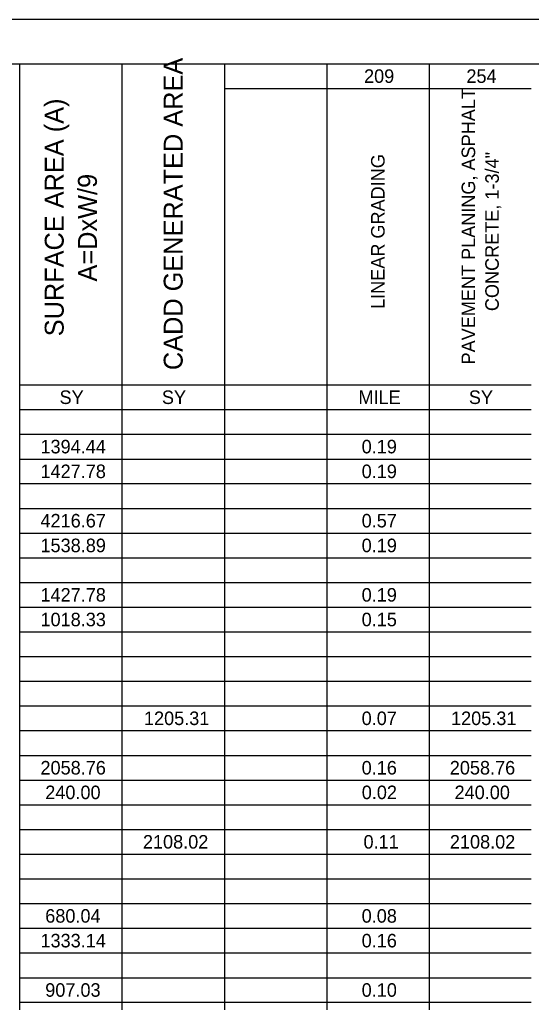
# Model space of a CAD drawing. Extents: x 0 to 34, y 0 to 22.
# Drawn here: x 10.58 to 16.38, y 10.87 to 22 of the extents above; entities that cross this region are included whole.
import ezdxf

# ---------------------------------------------------------------- set-up
doc = ezdxf.new("R2010")
doc.units = 0
for name, color, linetype in [('SH_Border', 7, 'Continuous'), ('SH_Cut_Line', 7, 'Continuous'), ('SH_Text', 7, 'Continuous')]:
    doc.layers.add(name, color=color, linetype=linetype)

msp = doc.modelspace()

# ---------------------------------------------------------------- linework, layer by layer
at = {"layer": 'SH_Border'}
msp.add_lwpolyline([(1.5, 21.5), (33.5, 21.5), (33.5, 0.5), (1.5, 0.5)], close=True, dxfattribs=at)
at = {"layer": 'SH_Cut_Line'}
msp.add_lwpolyline([(0, 0), (34, 0), (34, 22), (0, 22)], close=True, dxfattribs=at)
at = {"layer": 'SH_Text'}
for p, q in [((10.584, 21.5), (11.743, 21.5)), ((10.584, 21.5), (10.584, 21.22)), ((11.743, 21.5), (14.061, 21.5)), ((11.743, 21.5), (11.743, 21.22)), ((12.902, 21.5), (12.902, 21.22)), ((14.061, 21.5), (15.22, 21.5)), ((14.061, 21.5), (14.061, 21.22)), ((15.22, 21.5), (16.378, 21.5)), ((15.22, 21.5), (15.22, 21.22)), ((10.584, 21.22), (10.584, 20.941)), ((11.743, 21.22), (11.743, 20.941)), ((12.902, 21.22), (14.061, 21.22)), ((12.902, 21.22), (12.902, 20.941)), ((14.061, 21.22), (15.22, 21.22)), ((14.061, 21.22), (14.061, 20.941)), ((15.22, 21.22), (16.378, 21.22)), ((15.22, 21.22), (15.22, 20.941)), ((10.584, 20.941), (10.584, 20.661)), ((11.743, 20.941), (11.743, 20.661)), ((12.902, 20.941), (12.902, 20.661)), ((14.061, 20.941), (14.061, 20.661)), ((15.22, 20.941), (15.22, 20.661)), ((10.584, 20.661), (10.584, 20.381)), ((11.743, 20.661), (11.743, 20.381)), ((12.902, 20.661), (12.902, 20.381)), ((14.061, 20.661), (14.061, 20.381)), ((15.22, 20.661), (15.22, 20.381)), ((10.584, 20.381), (10.584, 20.101)), ((11.743, 20.381), (11.743, 20.101)), ((12.902, 20.381), (12.902, 20.101)), ((14.061, 20.381), (14.061, 20.101)), ((15.22, 20.381), (15.22, 20.101)), ((10.584, 20.101), (10.584, 19.822)), ((11.743, 20.101), (11.743, 19.822)), ((12.902, 20.101), (12.902, 19.822)), ((14.061, 20.101), (14.061, 19.822)), ((15.22, 20.101), (15.22, 19.822)), ((10.584, 19.822), (10.584, 19.542)), ((11.743, 19.822), (11.743, 19.542)), ((12.902, 19.822), (12.902, 19.542)), ((14.061, 19.822), (14.061, 19.542)), ((15.22, 19.822), (15.22, 19.542)), ((10.584, 19.542), (10.584, 19.262)), ((11.743, 19.542), (11.743, 19.262)), ((12.902, 19.542), (12.902, 19.262)), ((14.061, 19.542), (14.061, 19.262)), ((15.22, 19.542), (15.22, 19.262)), ((10.584, 19.262), (10.584, 18.983)), ((11.743, 19.262), (11.743, 18.983)), ((12.902, 19.262), (12.902, 18.983)), ((14.061, 19.262), (14.061, 18.983)), ((15.22, 19.262), (15.22, 18.983)), ((10.584, 18.983), (10.584, 18.703)), ((11.743, 18.983), (11.743, 18.703)), ((12.902, 18.983), (12.902, 18.703)), ((14.061, 18.983), (14.061, 18.703)), ((15.22, 18.983), (15.22, 18.703)), ((10.584, 18.703), (10.584, 18.423)), ((11.743, 18.703), (11.743, 18.423)), ((12.902, 18.703), (12.902, 18.423)), ((14.061, 18.703), (14.061, 18.423)), ((15.22, 18.703), (15.22, 18.423)), ((10.584, 18.423), (10.584, 18.143)), ((11.743, 18.423), (11.743, 18.143)), ((12.902, 18.423), (12.902, 18.143)), ((14.061, 18.423), (14.061, 18.143)), ((15.22, 18.423), (15.22, 18.143)), ((10.584, 18.143), (10.584, 17.864)), ((11.743, 18.143), (11.743, 17.864)), ((12.902, 18.143), (12.902, 17.864)), ((14.061, 18.143), (14.061, 17.864)), ((15.22, 18.143), (15.22, 17.864)), ((10.584, 17.864), (11.743, 17.864)), ((10.584, 17.864), (10.584, 17.584)), ((11.743, 17.864), (14.061, 17.864)), ((11.743, 17.864), (11.743, 17.584)), ((12.902, 17.864), (12.902, 17.584)), ((14.061, 17.864), (15.22, 17.864)), ((14.061, 17.864), (14.061, 17.584)), ((15.22, 17.864), (16.378, 17.864)), ((15.22, 17.864), (15.22, 17.584)), ((10.584, 17.584), (11.743, 17.584)), ((10.584, 17.584), (10.584, 17.304)), ((11.743, 17.584), (14.061, 17.584)), ((11.743, 17.584), (11.743, 17.304)), ((12.902, 17.584), (12.902, 17.304)), ((14.061, 17.584), (15.22, 17.584)), ((14.061, 17.584), (14.061, 17.304)), ((15.22, 17.584), (16.378, 17.584)), ((15.22, 17.584), (15.22, 17.304)), ((10.584, 17.304), (11.743, 17.304)), ((10.584, 17.304), (10.584, 17.024)), ((11.743, 17.304), (14.061, 17.304)), ((11.743, 17.304), (11.743, 17.024)), ((12.902, 17.304), (12.902, 17.024)), ((14.061, 17.304), (15.22, 17.304)), ((14.061, 17.304), (14.061, 17.024)), ((15.22, 17.304), (16.378, 17.304)), ((15.22, 17.304), (15.22, 17.024)), ((10.584, 17.024), (11.743, 17.024)), ((10.584, 17.024), (10.584, 16.745)), ((11.743, 17.024), (14.061, 17.024)), ((11.743, 17.024), (11.743, 16.745)), ((12.902, 17.024), (12.902, 16.745)), ((14.061, 17.024), (15.22, 17.024)), ((14.061, 17.024), (14.061, 16.745)), ((15.22, 17.024), (16.378, 17.024)), ((15.22, 17.024), (15.22, 16.745)), ((10.584, 16.745), (11.743, 16.745)), ((10.584, 16.745), (10.584, 16.465)), ((11.743, 16.745), (14.061, 16.745)), ((11.743, 16.745), (11.743, 16.465)), ((12.902, 16.745), (12.902, 16.465)), ((14.061, 16.745), (15.22, 16.745)), ((14.061, 16.745), (14.061, 16.465)), ((15.22, 16.745), (16.378, 16.745)), ((15.22, 16.745), (15.22, 16.465)), ((10.584, 16.465), (11.743, 16.465)), ((10.584, 16.465), (10.584, 16.185)), ((11.743, 16.465), (14.061, 16.465)), ((11.743, 16.465), (11.743, 16.185)), ((12.902, 16.465), (12.902, 16.185)), ((14.061, 16.465), (15.22, 16.465)), ((14.061, 16.465), (14.061, 16.185)), ((15.22, 16.465), (16.378, 16.465)), ((15.22, 16.465), (15.22, 16.185)), ((10.584, 16.185), (11.743, 16.185)), ((10.584, 16.185), (10.584, 15.906)), ((11.743, 16.185), (14.061, 16.185)), ((11.743, 16.185), (11.743, 15.906)), ((12.902, 16.185), (12.902, 15.906)), ((14.061, 16.185), (15.22, 16.185)), ((14.061, 16.185), (14.061, 15.906)), ((15.22, 16.185), (16.378, 16.185)), ((15.22, 16.185), (15.22, 15.906)), ((10.584, 15.906), (11.743, 15.906)), ((10.584, 15.906), (10.584, 15.626)), ((11.743, 15.906), (14.061, 15.906)), ((11.743, 15.906), (11.743, 15.626)), ((12.902, 15.906), (12.902, 15.626)), ((14.061, 15.906), (15.22, 15.906)), ((14.061, 15.906), (14.061, 15.626)), ((15.22, 15.906), (16.378, 15.906)), ((15.22, 15.906), (15.22, 15.626)), ((10.584, 15.626), (11.743, 15.626)), ((10.584, 15.626), (10.584, 15.346)), ((11.743, 15.626), (14.061, 15.626)), ((11.743, 15.626), (11.743, 15.346)), ((12.902, 15.626), (12.902, 15.346)), ((14.061, 15.626), (15.22, 15.626)), ((14.061, 15.626), (14.061, 15.346)), ((15.22, 15.626), (16.378, 15.626)), ((15.22, 15.626), (15.22, 15.346)), ((10.584, 15.346), (11.743, 15.346)), ((10.584, 15.346), (10.584, 15.066)), ((11.743, 15.346), (14.061, 15.346)), ((11.743, 15.346), (11.743, 15.066)), ((12.902, 15.346), (12.902, 15.066)), ((14.061, 15.346), (15.22, 15.346)), ((14.061, 15.346), (14.061, 15.066)), ((15.22, 15.346), (16.378, 15.346)), ((15.22, 15.346), (15.22, 15.066)), ((10.584, 15.066), (11.743, 15.066)), ((10.584, 15.066), (10.584, 14.787)), ((11.743, 15.066), (14.061, 15.066)), ((11.743, 15.066), (11.743, 14.787)), ((12.902, 15.066), (12.902, 14.787)), ((14.061, 15.066), (15.22, 15.066)), ((14.061, 15.066), (14.061, 14.787)), ((15.22, 15.066), (16.378, 15.066)), ((15.22, 15.066), (15.22, 14.787)), ((10.584, 14.787), (11.743, 14.787)), ((10.584, 14.787), (10.584, 14.507)), ((11.743, 14.787), (14.061, 14.787)), ((11.743, 14.787), (11.743, 14.507)), ((12.902, 14.787), (12.902, 14.507)), ((14.061, 14.787), (15.22, 14.787)), ((14.061, 14.787), (14.061, 14.507)), ((15.22, 14.787), (16.378, 14.787)), ((15.22, 14.787), (15.22, 14.507)), ((10.584, 14.507), (11.743, 14.507)), ((10.584, 14.507), (10.584, 14.227)), ((11.743, 14.507), (14.061, 14.507)), ((11.743, 14.507), (11.743, 14.227)), ((12.902, 14.507), (12.902, 14.227)), ((14.061, 14.507), (15.22, 14.507)), ((14.061, 14.507), (14.061, 14.227)), ((15.22, 14.507), (16.378, 14.507)), ((15.22, 14.507), (15.22, 14.227)), ((10.584, 14.227), (11.743, 14.227)), ((10.584, 14.227), (10.584, 13.948)), ((11.743, 14.227), (14.061, 14.227)), ((11.743, 14.227), (11.743, 13.948)), ((12.902, 14.227), (12.902, 13.948)), ((14.061, 14.227), (15.22, 14.227)), ((14.061, 14.227), (14.061, 13.948)), ((15.22, 14.227), (16.378, 14.227)), ((15.22, 14.227), (15.22, 13.948)), ((10.584, 13.948), (11.743, 13.948)), ((10.584, 13.948), (10.584, 13.668)), ((11.743, 13.948), (14.061, 13.948)), ((11.743, 13.948), (11.743, 13.668)), ((12.902, 13.948), (12.902, 13.668)), ((14.061, 13.948), (15.22, 13.948)), ((14.061, 13.948), (14.061, 13.668)), ((15.22, 13.948), (16.378, 13.948)), ((15.22, 13.948), (15.22, 13.668)), ((10.584, 13.668), (11.743, 13.668)), ((10.584, 13.668), (10.584, 13.388)), ((11.743, 13.668), (14.061, 13.668)), ((11.743, 13.668), (11.743, 13.388)), ((12.902, 13.668), (12.902, 13.388)), ((14.061, 13.668), (15.22, 13.668)), ((14.061, 13.668), (14.061, 13.388)), ((15.22, 13.668), (16.378, 13.668)), ((15.22, 13.668), (15.22, 13.388)), ((10.584, 13.388), (11.743, 13.388)), ((10.584, 13.388), (10.584, 13.108)), ((11.743, 13.388), (14.061, 13.388)), ((11.743, 13.388), (11.743, 13.108)), ((12.902, 13.388), (12.902, 13.108)), ((14.061, 13.388), (15.22, 13.388)), ((14.061, 13.388), (14.061, 13.108)), ((15.22, 13.388), (16.378, 13.388)), ((15.22, 13.388), (15.22, 13.108)), ((10.584, 13.108), (11.743, 13.108)), ((10.584, 13.108), (10.584, 12.829)), ((11.743, 13.108), (14.061, 13.108)), ((11.743, 13.108), (11.743, 12.829)), ((12.902, 13.108), (12.902, 12.829)), ((14.061, 13.108), (15.22, 13.108)), ((14.061, 13.108), (14.061, 12.829)), ((15.22, 13.108), (16.378, 13.108)), ((15.22, 13.108), (15.22, 12.829)), ((10.584, 12.829), (11.743, 12.829)), ((10.584, 12.829), (10.584, 12.549)), ((11.743, 12.829), (14.061, 12.829)), ((11.743, 12.829), (11.743, 12.549)), ((12.902, 12.829), (12.902, 12.549)), ((14.061, 12.829), (15.22, 12.829)), ((14.061, 12.829), (14.061, 12.549)), ((15.22, 12.829), (16.378, 12.829)), ((15.22, 12.829), (15.22, 12.549)), ((10.584, 12.549), (11.743, 12.549)), ((10.584, 12.549), (10.584, 12.269)), ((11.743, 12.549), (14.061, 12.549)), ((11.743, 12.549), (11.743, 12.269)), ((12.902, 12.549), (12.902, 12.269)), ((14.061, 12.549), (15.22, 12.549)), ((14.061, 12.549), (14.061, 12.269)), ((15.22, 12.549), (16.378, 12.549)), ((15.22, 12.549), (15.22, 12.269)), ((10.584, 12.269), (11.743, 12.269)), ((10.584, 12.269), (10.584, 11.99)), ((11.743, 12.269), (14.061, 12.269)), ((11.743, 12.269), (11.743, 11.99)), ((12.902, 12.269), (12.902, 11.99)), ((14.061, 12.269), (15.22, 12.269)), ((14.061, 12.269), (14.061, 11.99)), ((15.22, 12.269), (16.378, 12.269)), ((15.22, 12.269), (15.22, 11.99)), ((10.584, 11.99), (11.743, 11.99)), ((10.584, 11.99), (10.584, 11.71)), ((11.743, 11.99), (14.061, 11.99)), ((11.743, 11.99), (11.743, 11.71)), ((12.902, 11.99), (12.902, 11.71)), ((14.061, 11.99), (15.22, 11.99)), ((14.061, 11.99), (14.061, 11.71)), ((15.22, 11.99), (16.378, 11.99)), ((15.22, 11.99), (15.22, 11.71)), ((10.584, 11.71), (11.743, 11.71)), ((10.584, 11.71), (10.584, 11.43)), ((11.743, 11.71), (14.061, 11.71)), ((11.743, 11.71), (11.743, 11.43)), ((12.902, 11.71), (12.902, 11.43)), ((14.061, 11.71), (15.22, 11.71)), ((14.061, 11.71), (14.061, 11.43)), ((15.22, 11.71), (16.378, 11.71)), ((15.22, 11.71), (15.22, 11.43)), ((10.584, 11.43), (11.743, 11.43)), ((10.584, 11.43), (10.584, 11.15)), ((11.743, 11.43), (14.061, 11.43)), ((11.743, 11.43), (11.743, 11.15)), ((12.902, 11.43), (12.902, 11.15)), ((14.061, 11.43), (15.22, 11.43)), ((14.061, 11.43), (14.061, 11.15)), ((15.22, 11.43), (16.378, 11.43)), ((15.22, 11.43), (15.22, 11.15)), ((10.584, 11.15), (11.743, 11.15)), ((10.584, 11.15), (10.584, 10.871)), ((11.743, 11.15), (14.061, 11.15)), ((11.743, 11.15), (11.743, 10.871)), ((12.902, 11.15), (12.902, 10.871)), ((14.061, 11.15), (15.22, 11.15)), ((14.061, 11.15), (14.061, 10.871)), ((15.22, 11.15), (16.378, 11.15)), ((15.22, 11.15), (15.22, 10.871)), ((10.584, 10.871), (11.743, 10.871)), ((10.584, 10.871), (10.584, 10.591)), ((11.743, 10.871), (14.061, 10.871)), ((11.743, 10.871), (11.743, 10.591)), ((12.902, 10.871), (12.902, 10.591)), ((14.061, 10.871), (15.22, 10.871)), ((14.061, 10.871), (14.061, 10.591)), ((15.22, 10.871), (16.378, 10.871)), ((15.22, 10.871), (15.22, 10.591))]:
    msp.add_line(p, q, dxfattribs=at)

# ---------------------------------------------------------------- texts
for s, height, p in [('CADD GENERATED AREA', 0.21445, (12.43, 18.031)), ('PAVEMENT PLANING, ASPHALT ', 0.15318, (15.742, 18.095)), ('SURFACE AREA (A) ', 0.21445, (11.083, 18.414)), ('CONCRETE, 1-3/4"', 0.15318, (16.01, 18.699)), ('LINEAR GRADING', 0.15318, (14.717, 18.724)), ('A=DxW/9', 0.2145, (11.459, 19.034))]:
    msp.add_text(s, height=height, rotation=90, dxfattribs=at).set_placement(p)
for s, p in [('209', (14.484, 21.284)), ('254', (15.643, 21.284)), ('SY', (11.036, 17.647)), ('SY', (12.195, 17.647)), ('MILE', (14.421, 17.647)), ('SY', (15.671, 17.647)), ('1394.44', (10.82, 17.088)), ('0.19', (14.457, 17.088)), ('1427.78', (10.82, 16.808)), ('0.19', (14.457, 16.808)), ('4216.67', (10.82, 16.249)), ('0.57', (14.457, 16.249)), ('1538.89', (10.82, 15.969)), ('0.19', (14.457, 15.969)), ('1427.78', (10.82, 15.409)), ('0.19', (14.457, 15.409)), ('1018.33', (10.82, 15.13)), ('0.15', (14.457, 15.13)), ('1205.31', (11.992, 14.011)), ('0.07', (14.457, 14.011)), ('1205.31', (15.469, 14.011)), ('2058.76', (10.82, 13.451)), ('0.16', (14.457, 13.451)), ('2058.76', (15.455, 13.451)), ('240.00', (10.874, 13.172)), ('0.02', (14.458, 13.172)), ('240.00', (15.509, 13.172)), ('2108.02', (11.98, 12.612)), ('0.11', (14.478, 12.612)), ('2108.02', (15.456, 12.612)), ('680.04', (10.874, 11.773)), ('0.08', (14.457, 11.773)), ('1333.14', (10.82, 11.493)), ('0.16', (14.457, 11.493)), ('907.03', (10.874, 10.934)), ('0.10', (14.457, 10.934))]:
    msp.add_text(s, height=0.1532, dxfattribs=at).set_placement(p)

doc.saveas('drawing.dxf')
